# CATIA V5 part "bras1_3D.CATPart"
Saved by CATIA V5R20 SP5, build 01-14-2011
Part number: manivelle_3D
Publications: "diametre_maneton"
Bounding box of the stored display mesh (mm): x -20 to 10, y -93 to 113, z -103 to 103
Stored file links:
  D:\thinkmotion-MPB\Dropbox\IAO_2011\MMS_GR1\0\IAO_2011_1470_mpeyrard\mpeyrard\mpeyrard\mpeyrard\IAO_2011_1470_mpeyrard\bras1_3D.CATPart
  D:\thinkmotion-MPB\Dropbox\IAO_2011\MMS_GR1\0\IAO_2011_1470_mpeyrard\mpeyrard\mpeyrard\mpeyrard\IAO_2011_1470_mpeyrard\mpeyrard.CATProduct
  D:\thinkmotion-MPB\Dropbox\IAO_2011\MMS_GR1\0\IAO_2011_1470_mpeyrard\mpeyrard\mpeyrard\mpeyrard\IAO_2011_1470_mpeyrard\squeletten_bras1.CATPart
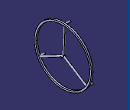
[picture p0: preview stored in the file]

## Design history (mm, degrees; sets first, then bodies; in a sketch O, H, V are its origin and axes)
Parameters
  diametre_maneton = 6 mm
External parameters (linked from other documents)
  External.excentrique = 100 mm
Set1
  Point1: linked copy from another document
  Point2: linked copy from another document
  Plane1: linked copy from another document
  Point3: linked copy from another document
  Point4: linked copy from another document
  Plane2: linked copy from another document
  Line1 to Line5: linked copy from another document
Set2
  Line6: type PtDir, RefPoint Point1, Direction Plane1, Start -20, End 20
  Line7: type PtDir, RefPoint Point2, Direction Plane1, Start -20, End 20
Body1 (main body)
  Sketch1 on Plane1, origin (0, 0, 0), H (0, 1, 0), V (0, 0, 1)
    line L1 (10, 0) -> (94.4328, -53.5827)
    point P1 (10, 0)
    point P2 (94.4328, -53.5827)
    line L2 (94.4328, -53.5827) -> (92.8253, -56.1157)
    line L3 (92.8253, -56.1157) -> (8.3925, -2.533)
    line L4 (8.3925, -2.533) -> (10, 0)
    reference projected point E1 (10, 0) from Point1
    reference projected point E2 (94.4328, -53.5827) from Point2
    angle L2 L1 = 90
    distance P1 E1 = 0
    distance P2 E2 = 0
    length L2 = 3
    parallelism: L4 L2, L1 L3
  Shaft1: profile Sketch1, axis edge of Sketch1, angle 360
  Sketch2 on Plane1, origin (0, 0, 0), H (0, 1, 0), V (0, 0, 1)
    circle A1 centre (10, 0) radius 3
    point P1 (10, 0)
    reference projected point E1 (10, 0) from Point1
    point P2 (94.4328, -53.5827)
    reference projected point E2 (94.4328, -53.5827) from Point2
    distance E1 P1 = 0
    distance P2 E2 = 0
  Pad1 "Axe_extrusion": profile Sketch2, direction (1, 0, 0), length 10, opposite side length 3
  Sketch3 on Plane1, origin (0, 0, 0), H (0, 1, 0), V (0, 0, 1)
    circle A1 centre (94.4328, -53.5827) radius 3
    point P1 (94.4328, -53.5827)
    reference projected point E1 (94.4328, -53.5827) from Point2
    circle A2 centre (-78.6204, -46.3296) radius 3
    point P2 (-78.6204, -46.3296)
    circle A3 centre (14.1876, 99.9123) radius 3
    point P3 (14.1876, 99.9123)
    reference projected point E2 (-78.6204, -46.3296) from Point3
    reference projected point E3 (14.1876, 99.9123) from Point4
    distance P1 E1 = 0
    distance P2 E2 = 0
    distance P3 E3 = 0
    radius A1 = 3 {= diametre_maneton/2}
    radius A2 = 3 {= diametre_maneton/2}
    radius A3 = 3 {= diametre_maneton/2}
  Pad2 "Maneton_Extrusion": profile Sketch3, direction (-1, 0, 0), length 20, opposite side length 3
  Sketch4 on Plane2, origin (0, 0, 0), H (0, 1, 0), V (0, 0, 1)
    line L1 (10, 0) -> (-78.6204, -46.3296)
    line L2 (-78.6204, -46.3296) -> (-77.2305, -48.9882)
    line L3 (-77.2305, -48.9882) -> (11.3899, -2.6586)
    line L4 (11.3899, -2.6586) -> (10, 0)
    reference projected point E1 (-78.6204, -46.3296) from Line1
    reference projected line E2 (10, 0) -> (-78.6204, -46.3296) from Line2
    reference projected line E3 (10, 0) -> (-78.6204, -46.3296) from Line2
    reference projected point E4 (10, 0) from Line3
    length L4 = 3
    distance L2 E1 = 0
    distance L1 E3 = 0
    distance E4 L4 = 0
    perpendicularity: L2 L1, L3 L2
    parallelism: L4 L2, L1 E2
  Shaft2: profile Sketch4, axis Line2, angle 360
  Sketch5 on Plane2, origin (0, 0, 0), H (0, 1, 0), V (0, 0, 1)
    line L1 (12.9974, -0.1256) -> (10, 0)
    line L2 (10, 0) -> (14.1876, 99.9123)
    line L3 (14.1876, 99.9123) -> (17.1849, 99.7867)
    line L4 (17.1849, 99.7867) -> (12.9974, -0.1256)
    reference projected line E1 (14.1876, 99.9123) -> (13.1407, 74.9342) from Line5
    reference projected line E2 (14.1876, 99.9123) -> (13.1407, 74.9342) from Line5
    reference projected point E4 (10, 0) from Line3
    reference projected point E5 (14.1876, 99.9123) from Line4
    length L1 = 3
    distance E2 L2 = 0
    distance L1 E4 = 0
    distance E5 L3 = 0
    parallelism: L1 L3, L4 L2, L2 E1
    perpendicularity: L1 L4
  Shaft3: profile Sketch5, axis Line5, angle 360
  Sketch6 on Plane2, origin (0, 0, 0), H (0, 1, 0), V (0, 0, 1)
    circle A1 centre (10, 0) radius 97
    point P1 (10, 0)
    reference projected point E1 (10, 0) from Line3
    circle A2 centre (10, 0) radius 103
    radius A1 = 97 {= External.excentrique-3mm}
    distance P1 E1 = 0
    radius A2 = 103 {= External.excentrique+3mm}
    coincidence: P1 H
  Pad3: profile Sketch6, direction (1, 0, 0), length 3, mirrored extent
